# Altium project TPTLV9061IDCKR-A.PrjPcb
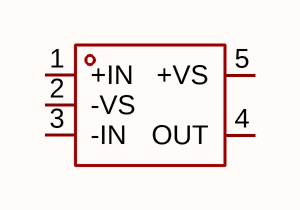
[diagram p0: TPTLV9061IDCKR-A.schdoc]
1 sheet, 1 parts. Net scope: global (net labels, ports and power ports of the same name join across sheets).

## Sheet TPTLV9061IDCKR-A.schdoc
size 127 x 101 mm

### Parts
U?  tptlv9061idckr-a  [SOT-23-5_L2.9-W1.6-P0.95-LS2.8-BL]  (value not drawn)

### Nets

Not connected (* = marked no-connect by the designer): U? 1(+IN) 2(-VS) 3(-IN) 4(OUT) 5(+VS)

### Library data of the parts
U? = tptlv9061idckr-a: Manufacturer: TECH PUBLIC(台舟); AddInBom: yes; ModelId: 018c57e721114987ae90467fe9f1d259; ModelTransform: 114.96,110.236,0,0,0,0,0,0,0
